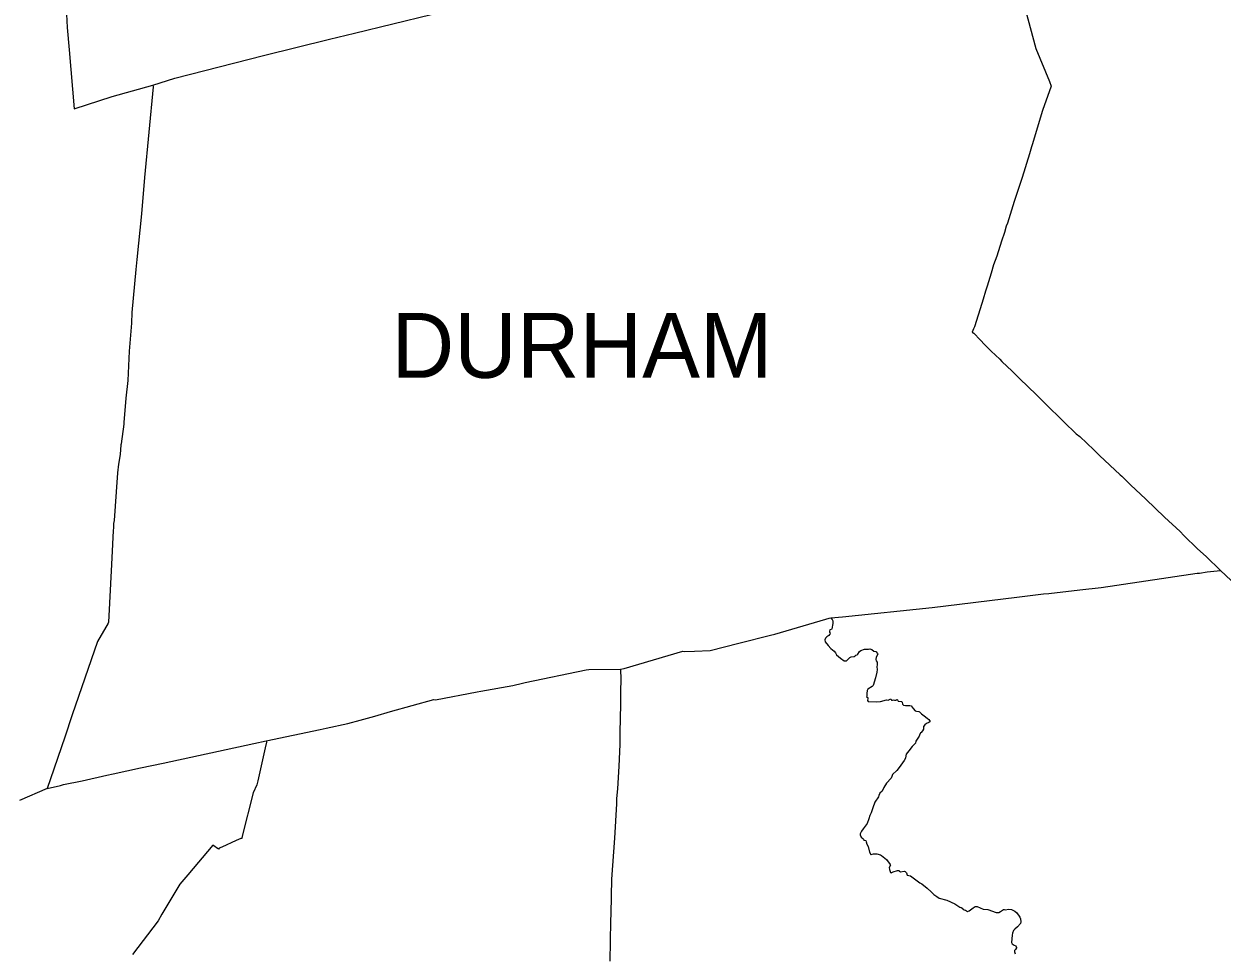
# Model space of a CAD drawing. Extents: x 0 to 2603, y -226 to 830.
# Drawn here: x 192.1 to 217.02, y 555.67 to 575 of the extents above; entities that cross this region are included whole.
import ezdxf

# ---------------------------------------------------------------- set-up
doc = ezdxf.new("R2010")
doc.units = 0
for name, color, linetype in [('CT_TSH_Map_Districts', 7, 'Continuous'), ('CT_TSH_Map_Town_Limits', 7, 'Continuous'), ('CT_TSH_Map_Town_Text', 7, 'Continuous')]:
    doc.layers.add(name, color=color, linetype=linetype)

msp = doc.modelspace()

# ---------------------------------------------------------------- linework, layer by layer
at = {"layer": 'CT_TSH_Map_Districts'}
for points in [[(192.851, 576.685), (192.932, 575.851), (192.974, 575.341), (192.998, 574.92), (193.038, 574.456), (193.141, 573.228), (193.934, 573.484), (194.783, 573.725)], [(212.888, 575.462), (213.152, 574.484), (213.437, 573.798), (213.466, 573.703), (213.29, 573.198), (213.222, 572.965), (213.079, 572.5), (213.057, 572.44), (213.019, 572.295), (212.864, 571.8), (212.699, 571.306), (212.56, 570.854), (212.532, 570.789), (212.496, 570.661), (212.433, 570.48), (212.338, 570.169), (212.272, 569.983), (212.221, 569.815), (212.14, 569.544), (212.103, 569.435), (212.054, 569.268), (212.023, 569.182), (211.877, 568.698), (211.856, 568.654), (211.828, 568.582), (211.857, 568.565), (211.994, 568.425), (212.087, 568.321), (212.219, 568.186), (212.4, 568.021), (212.441, 567.973), (212.656, 567.775), (212.809, 567.619), (213.164, 567.281), (213.262, 567.182), (213.806, 566.644), (213.916, 566.547), (213.991, 566.472), (214.062, 566.412), (214.359, 566.137), (214.477, 566.018), (214.904, 565.615), (214.936, 565.589), (215.122, 565.412), (215.441, 565.11), (215.83, 564.737), (216.152, 564.435), (216.229, 564.353), (216.515, 564.081), (216.692, 563.915), (216.995, 563.63)], [(194.783, 573.725), (194.788, 573.688), (194.609, 571.802), (194.541, 571.046), (194.45, 570.093), (194.427, 569.891), (194.341, 568.991), (194.333, 568.775), (194.289, 568.188), (194.257, 567.581), (194.22, 567.21), (194.177, 566.706), (194.173, 566.672), (194.123, 566.26), (194.115, 566.238), (194.098, 566.041), (194.068, 565.837), (194.048, 565.66), (194.019, 565.265), (193.973, 564.67), (193.964, 564.608), (193.959, 564.516), (193.955, 564.462), (193.924, 563.889), (193.868, 562.814), (193.854, 562.555), (193.85, 562.532), (193.627, 562.152), (193.104, 560.625), (192.949, 560.158), (192.65, 559.293), (192.582, 559.09)], [(208.886, 562.64), (209.13, 562.666), (210.99, 562.858), (212.757, 563.071), (213.306, 563.139), (213.419, 563.148), (214.064, 563.224), (214.51, 563.273), (215.303, 563.388), (216.503, 563.569), (216.553, 563.574), (216.714, 563.597), (216.995, 563.63)], [(204.509, 561.575), (204.585, 561.589), (205.809, 561.946), (205.838, 561.944), (206.049, 561.952), (206.377, 561.961), (206.971, 562.112), (207.629, 562.284), (207.72, 562.304), (208.781, 562.618), (208.848, 562.635), (208.886, 562.64)], [(208.886, 562.64), (208.913, 562.608), (208.929, 562.577), (208.93, 562.527), (208.905, 562.411), (208.896, 562.398), (208.867, 562.39), (208.854, 562.368), (208.86, 562.344), (208.872, 562.328), (208.863, 562.3), (208.84, 562.278), (208.802, 562.25), (208.772, 562.218), (208.763, 562.185), (208.77, 562.143), (208.829, 562.07), (208.888, 562.003), (208.955, 561.95), (208.983, 561.916), (209.005, 561.872), (209.089, 561.802), (209.164, 561.751), (209.188, 561.745), (209.21, 561.749), (209.247, 561.78), (209.281, 561.819), (209.309, 561.834), (209.368, 561.838), (209.39, 561.855), (209.407, 561.865), (209.431, 561.872), (209.448, 561.886), (209.483, 561.944), (209.507, 561.962), (209.586, 561.992), (209.635, 561.993), (209.668, 561.988), (209.699, 561.997), (209.739, 561.985), (209.778, 561.952), (209.818, 561.945), (209.857, 561.898), (209.861, 561.884), (209.829, 561.821), (209.819, 561.777), (209.825, 561.751), (209.851, 561.721), (209.851, 561.666), (209.844, 561.626), (209.848, 561.566), (209.84, 561.515), (209.817, 561.393), (209.765, 561.237), (209.745, 561.215), (209.656, 561.156), (209.644, 561.129), (209.635, 561.069), (209.634, 561.006), (209.63, 560.99), (209.652, 560.982), (209.656, 560.966), (209.651, 560.924), (209.664, 560.905), (209.838, 560.896), (209.915, 560.903), (210.04, 560.935), (210.075, 560.932), (210.093, 560.934), (210.135, 560.954), (210.15, 560.932), (210.166, 560.931), (210.189, 560.94), (210.211, 560.929), (210.234, 560.931), (210.256, 560.944), (210.269, 560.935), (210.288, 560.909), (210.358, 560.902), (210.369, 560.89), (210.378, 560.845), (210.394, 560.826), (210.44, 560.817), (210.529, 560.819), (210.553, 560.811), (210.596, 560.754), (210.639, 560.708), (210.665, 560.699), (210.713, 560.692), (210.73, 560.684), (210.77, 560.642), (210.829, 560.605), (210.886, 560.557), (210.926, 560.53), (210.944, 560.499), (210.942, 560.479), (210.927, 560.467), (210.877, 560.442), (210.84, 560.417), (210.815, 560.383), (210.811, 560.325)], [(197.137, 560.085), (198.262, 560.322), (198.388, 560.345), (198.835, 560.442), (199.091, 560.515), (199.399, 560.599), (199.724, 560.691), (200.629, 560.943), (200.661, 560.939), (201.524, 561.1), (201.601, 561.118), (202.269, 561.237), (202.469, 561.28), (202.528, 561.297), (203.792, 561.563), (203.847, 561.567), (204.509, 561.575)], [(210.811, 560.325), (210.792, 560.291), (210.766, 560.26), (210.748, 560.247), (210.728, 560.205), (210.721, 560.182), (210.651, 560.074), (210.645, 560.032), (210.629, 560.011), (210.576, 559.966), (210.51, 559.877), (210.452, 559.809), (210.443, 559.769), (210.441, 559.726), (210.411, 559.678), (210.308, 559.528), (210.26, 559.465), (210.17, 559.384), (210.154, 559.343), (210.143, 559.31), (210.045, 559.202), (209.988, 559.116), (209.952, 559.04), (209.902, 558.997), (209.887, 558.947), (209.874, 558.921), (209.797, 558.811), (209.759, 558.692), (209.723, 558.588), (209.696, 558.534), (209.677, 558.459), (209.642, 558.365), (209.56, 558.253), (209.52, 558.204), (209.496, 558.151), (209.495, 558.126), (209.516, 558.083), (209.55, 558.052), (209.563, 558.038), (209.573, 558.018), (209.61, 558.008), (209.623, 557.983), (209.632, 557.933), (209.66, 557.884), (209.689, 557.769), (209.714, 557.722), (209.723, 557.716), (209.773, 557.734), (209.845, 557.736), (209.92, 557.714), (209.936, 557.697), (210.045, 557.617), (210.118, 557.509), (210.123, 557.495), (210.1, 557.449), (210.104, 557.41), (210.127, 557.343), (210.14, 557.338), (210.18, 557.356), (210.275, 557.388), (210.297, 557.385), (210.315, 557.372), (210.337, 557.359), (210.409, 557.37), (210.434, 557.364), (210.457, 557.337), (210.475, 557.292), (210.544, 557.273), (210.739, 557.133), (210.78, 557.108), (210.886, 557.016), (210.971, 556.946), (211.027, 556.89), (211.088, 556.844), (211.142, 556.814), (211.295, 556.769), (211.463, 556.69), (211.568, 556.621), (211.598, 556.614), (211.62, 556.602), (211.64, 556.572), (211.662, 556.567), (211.689, 556.562), (211.727, 556.537), (211.764, 556.548), (211.846, 556.611), (211.891, 556.635), (211.929, 556.635), (212.057, 556.581), (212.148, 556.576), (212.323, 556.513), (212.378, 556.516), (212.414, 556.533), (212.476, 556.575), (212.493, 556.573), (212.509, 556.566), (212.589, 556.583), (212.646, 556.577), (212.67, 556.56), (212.715, 556.539), (212.754, 556.505)], [(192.582, 559.09), (192.857, 559.153), (192.923, 559.172), (193.307, 559.252), (193.826, 559.372), (193.951, 559.394), (194.521, 559.524), (194.996, 559.622), (196.879, 560.031), (197.137, 560.085)], [(212.754, 556.505), (212.815, 556.416), (212.831, 556.38), (212.84, 556.318), (212.833, 556.282), (212.771, 556.216), (212.714, 556.167), (212.687, 556.135), (212.667, 556.084), (212.658, 556.044), (212.646, 555.889), (212.659, 555.86), (212.702, 555.836), (212.734, 555.82), (212.746, 555.786), (212.745, 555.775), (212.727, 555.746), (212.706, 555.722), (212.704, 555.697), (212.722, 555.651)]]:
    msp.add_lwpolyline(points, dxfattribs=at)
at = {"layer": 'CT_TSH_Map_Town_Limits'}
for points in [[(192.851, 576.685), (192.932, 575.851), (192.974, 575.341), (192.998, 574.92), (193.038, 574.456), (193.141, 573.228), (193.934, 573.484), (194.783, 573.725)], [(194.783, 573.725), (195.239, 573.867), (196.787, 574.266), (197.08, 574.342), (198.457, 574.678), (198.972, 574.803), (200.568, 575.196), (201.372, 575.395), (201.402, 575.399), (201.52, 575.42), (201.769, 575.446), (202.038, 575.482), (202.678, 575.562), (203.154, 575.653), (203.956, 575.759), (204.177, 575.791), (204.396, 575.838), (204.682, 576.321)], [(212.888, 575.462), (213.152, 574.484), (213.437, 573.798), (213.466, 573.703), (213.29, 573.198), (213.222, 572.965), (213.079, 572.5), (213.057, 572.44), (213.019, 572.295), (212.864, 571.8), (212.699, 571.306), (212.56, 570.854), (212.532, 570.789), (212.496, 570.661), (212.433, 570.48), (212.338, 570.169), (212.272, 569.983), (212.221, 569.815), (212.14, 569.544), (212.103, 569.435), (212.054, 569.268), (212.023, 569.182), (211.877, 568.698), (211.856, 568.654), (211.828, 568.582), (211.857, 568.565), (211.994, 568.425), (212.087, 568.321), (212.219, 568.186), (212.4, 568.021), (212.441, 567.973), (212.656, 567.775), (212.809, 567.619), (213.164, 567.281), (213.262, 567.182), (213.806, 566.644), (213.916, 566.547), (213.991, 566.472), (214.062, 566.412), (214.359, 566.137), (214.477, 566.018), (214.904, 565.615), (214.936, 565.589), (215.122, 565.412), (215.441, 565.11), (215.83, 564.737), (216.152, 564.435), (216.229, 564.353), (216.515, 564.081), (216.692, 563.915), (216.995, 563.63)], [(194.783, 573.725), (194.788, 573.688), (194.609, 571.802), (194.541, 571.046), (194.45, 570.093), (194.427, 569.891), (194.341, 568.991), (194.333, 568.775), (194.289, 568.188), (194.257, 567.581), (194.22, 567.21), (194.177, 566.706), (194.173, 566.672), (194.123, 566.26), (194.115, 566.238), (194.098, 566.041), (194.068, 565.837), (194.048, 565.66), (194.019, 565.265), (193.973, 564.67), (193.964, 564.608), (193.959, 564.516), (193.955, 564.462), (193.924, 563.889), (193.868, 562.814), (193.854, 562.555), (193.85, 562.532), (193.627, 562.152), (193.104, 560.625), (192.949, 560.158), (192.65, 559.293), (192.582, 559.09)], [(208.886, 562.64), (209.13, 562.666), (210.99, 562.858), (212.757, 563.071), (213.306, 563.139), (213.419, 563.148), (214.064, 563.224), (214.51, 563.273), (215.303, 563.388), (216.503, 563.569), (216.553, 563.574), (216.714, 563.597), (216.995, 563.63)], [(216.995, 563.63), (217.426, 563.218), (218.532, 562.143), (219.586, 561.102), (219.781, 560.912), (220.591, 560.122), (220.727, 559.996), (221.487, 559.251), (223.722, 557.075), (224.706, 557.371), (226.035, 557.777), (227.513, 558.224), (227.776, 558.298), (229.25, 558.754)], [(204.509, 561.575), (204.585, 561.589), (205.809, 561.946), (205.838, 561.944), (206.049, 561.952), (206.377, 561.961), (206.971, 562.112), (207.629, 562.284), (207.72, 562.304), (208.781, 562.618), (208.848, 562.635), (208.886, 562.64)], [(208.886, 562.64), (208.913, 562.608), (208.929, 562.577), (208.93, 562.527), (208.905, 562.411), (208.896, 562.398), (208.867, 562.39), (208.854, 562.368), (208.86, 562.344), (208.872, 562.328), (208.863, 562.3), (208.84, 562.278), (208.802, 562.25), (208.772, 562.218), (208.763, 562.185), (208.77, 562.143), (208.829, 562.07), (208.888, 562.003), (208.955, 561.95), (208.983, 561.916), (209.005, 561.872), (209.089, 561.802), (209.164, 561.751), (209.188, 561.745), (209.21, 561.749), (209.247, 561.78), (209.281, 561.819), (209.309, 561.834), (209.368, 561.838), (209.39, 561.855), (209.407, 561.865), (209.431, 561.872), (209.448, 561.886), (209.483, 561.944), (209.507, 561.962), (209.586, 561.992), (209.635, 561.993), (209.668, 561.988), (209.699, 561.997), (209.739, 561.985), (209.778, 561.952), (209.818, 561.945), (209.857, 561.898), (209.861, 561.884), (209.829, 561.821), (209.819, 561.777), (209.825, 561.751), (209.851, 561.721), (209.851, 561.666), (209.844, 561.626), (209.848, 561.566), (209.84, 561.515), (209.817, 561.393), (209.765, 561.237), (209.745, 561.215), (209.656, 561.156), (209.644, 561.129), (209.635, 561.069), (209.634, 561.006), (209.63, 560.99), (209.652, 560.982), (209.656, 560.966), (209.651, 560.924), (209.664, 560.905), (209.838, 560.896), (209.915, 560.903), (210.04, 560.935), (210.075, 560.932), (210.093, 560.934), (210.135, 560.954), (210.15, 560.932), (210.166, 560.931), (210.189, 560.94), (210.211, 560.929), (210.234, 560.931), (210.256, 560.944), (210.269, 560.935), (210.288, 560.909), (210.358, 560.902), (210.369, 560.89), (210.378, 560.845), (210.394, 560.826), (210.44, 560.817), (210.529, 560.819), (210.553, 560.811), (210.596, 560.754), (210.639, 560.708), (210.665, 560.699), (210.713, 560.692), (210.73, 560.684), (210.77, 560.642), (210.829, 560.605), (210.886, 560.557), (210.926, 560.53), (210.944, 560.499), (210.942, 560.479), (210.927, 560.467), (210.877, 560.442), (210.84, 560.417), (210.815, 560.383), (210.811, 560.325)], [(197.137, 560.085), (198.262, 560.322), (198.388, 560.345), (198.835, 560.442), (199.091, 560.515), (199.399, 560.599), (199.724, 560.691), (200.629, 560.943), (200.661, 560.939), (201.524, 561.1), (201.601, 561.118), (202.269, 561.237), (202.469, 561.28), (202.528, 561.297), (203.792, 561.563), (203.847, 561.567), (204.509, 561.575)], [(204.509, 561.575), (204.514, 561.36), (204.507, 561.115), (204.507, 560.849), (204.498, 560.26), (204.496, 560.009), (204.477, 559.556), (204.449, 559.086), (204.429, 558.882), (204.428, 558.775), (204.383, 558.06), (204.321, 557.204), (204.31, 556.49), (204.301, 556.334), (204.284, 555.503)], [(210.811, 560.325), (210.792, 560.291), (210.766, 560.26), (210.748, 560.247), (210.728, 560.205), (210.721, 560.182), (210.651, 560.074), (210.645, 560.032), (210.629, 560.011), (210.576, 559.966), (210.51, 559.877), (210.452, 559.809), (210.443, 559.769), (210.441, 559.726), (210.411, 559.678), (210.308, 559.528), (210.26, 559.465), (210.17, 559.384), (210.154, 559.343), (210.143, 559.31), (210.045, 559.202), (209.988, 559.116), (209.952, 559.04), (209.902, 558.997), (209.887, 558.947), (209.874, 558.921), (209.797, 558.811), (209.759, 558.692), (209.723, 558.588), (209.696, 558.534), (209.677, 558.459), (209.642, 558.365), (209.56, 558.253), (209.52, 558.204), (209.496, 558.151), (209.495, 558.126), (209.516, 558.083), (209.55, 558.052), (209.563, 558.038), (209.573, 558.018), (209.61, 558.008), (209.623, 557.983), (209.632, 557.933), (209.66, 557.884), (209.689, 557.769), (209.714, 557.722), (209.723, 557.716), (209.773, 557.734), (209.845, 557.736), (209.92, 557.714), (209.936, 557.697), (210.045, 557.617), (210.118, 557.509), (210.123, 557.495), (210.1, 557.449), (210.104, 557.41), (210.127, 557.343), (210.14, 557.338), (210.18, 557.356), (210.275, 557.388), (210.297, 557.385), (210.315, 557.372), (210.337, 557.359), (210.409, 557.37), (210.434, 557.364), (210.457, 557.337), (210.475, 557.292), (210.544, 557.273), (210.739, 557.133), (210.78, 557.108), (210.886, 557.016), (210.971, 556.946), (211.027, 556.89), (211.088, 556.844), (211.142, 556.814), (211.295, 556.769), (211.463, 556.69), (211.568, 556.621), (211.598, 556.614), (211.62, 556.602), (211.64, 556.572), (211.662, 556.567), (211.689, 556.562), (211.727, 556.537), (211.764, 556.548), (211.846, 556.611), (211.891, 556.635), (211.929, 556.635), (212.057, 556.581), (212.148, 556.576), (212.323, 556.513), (212.378, 556.516), (212.414, 556.533), (212.476, 556.575), (212.493, 556.573), (212.509, 556.566), (212.589, 556.583), (212.646, 556.577), (212.67, 556.56), (212.715, 556.539), (212.754, 556.505)], [(192.582, 559.09), (192.857, 559.153), (192.923, 559.172), (193.307, 559.252), (193.826, 559.372), (193.951, 559.394), (194.521, 559.524), (194.996, 559.622), (196.879, 560.031), (197.137, 560.085)], [(197.137, 560.085), (197.146, 560.056), (197.12, 559.937), (196.966, 559.252), (196.946, 559.165), (196.864, 559.005), (196.64, 558.101), (196.63, 558.051), (196.608, 558.052), (196.511, 558.011), (196.212, 557.87), (196.161, 557.852), (196.146, 557.827), (196.031, 557.914), (195.509, 557.298), (195.343, 557.101), (194.97, 556.48), (194.89, 556.34), (194.358, 555.641)], [(192.582, 559.09), (192.004, 558.841)], [(212.754, 556.505), (212.815, 556.416), (212.831, 556.38), (212.84, 556.318), (212.833, 556.282), (212.771, 556.216), (212.714, 556.167), (212.687, 556.135), (212.667, 556.084), (212.658, 556.044), (212.646, 555.889), (212.659, 555.86), (212.702, 555.836), (212.734, 555.82), (212.746, 555.786), (212.745, 555.775), (212.727, 555.746), (212.706, 555.722), (212.704, 555.697), (212.722, 555.651)]]:
    msp.add_lwpolyline(points, dxfattribs=at)

# ---------------------------------------------------------------- texts
at = {"layer": 'CT_TSH_Map_Town_Text'}
msp.add_text('DURHAM', height=1.35, dxfattribs=at).set_placement((199.745, 567.635))

doc.saveas('drawing.dxf')
